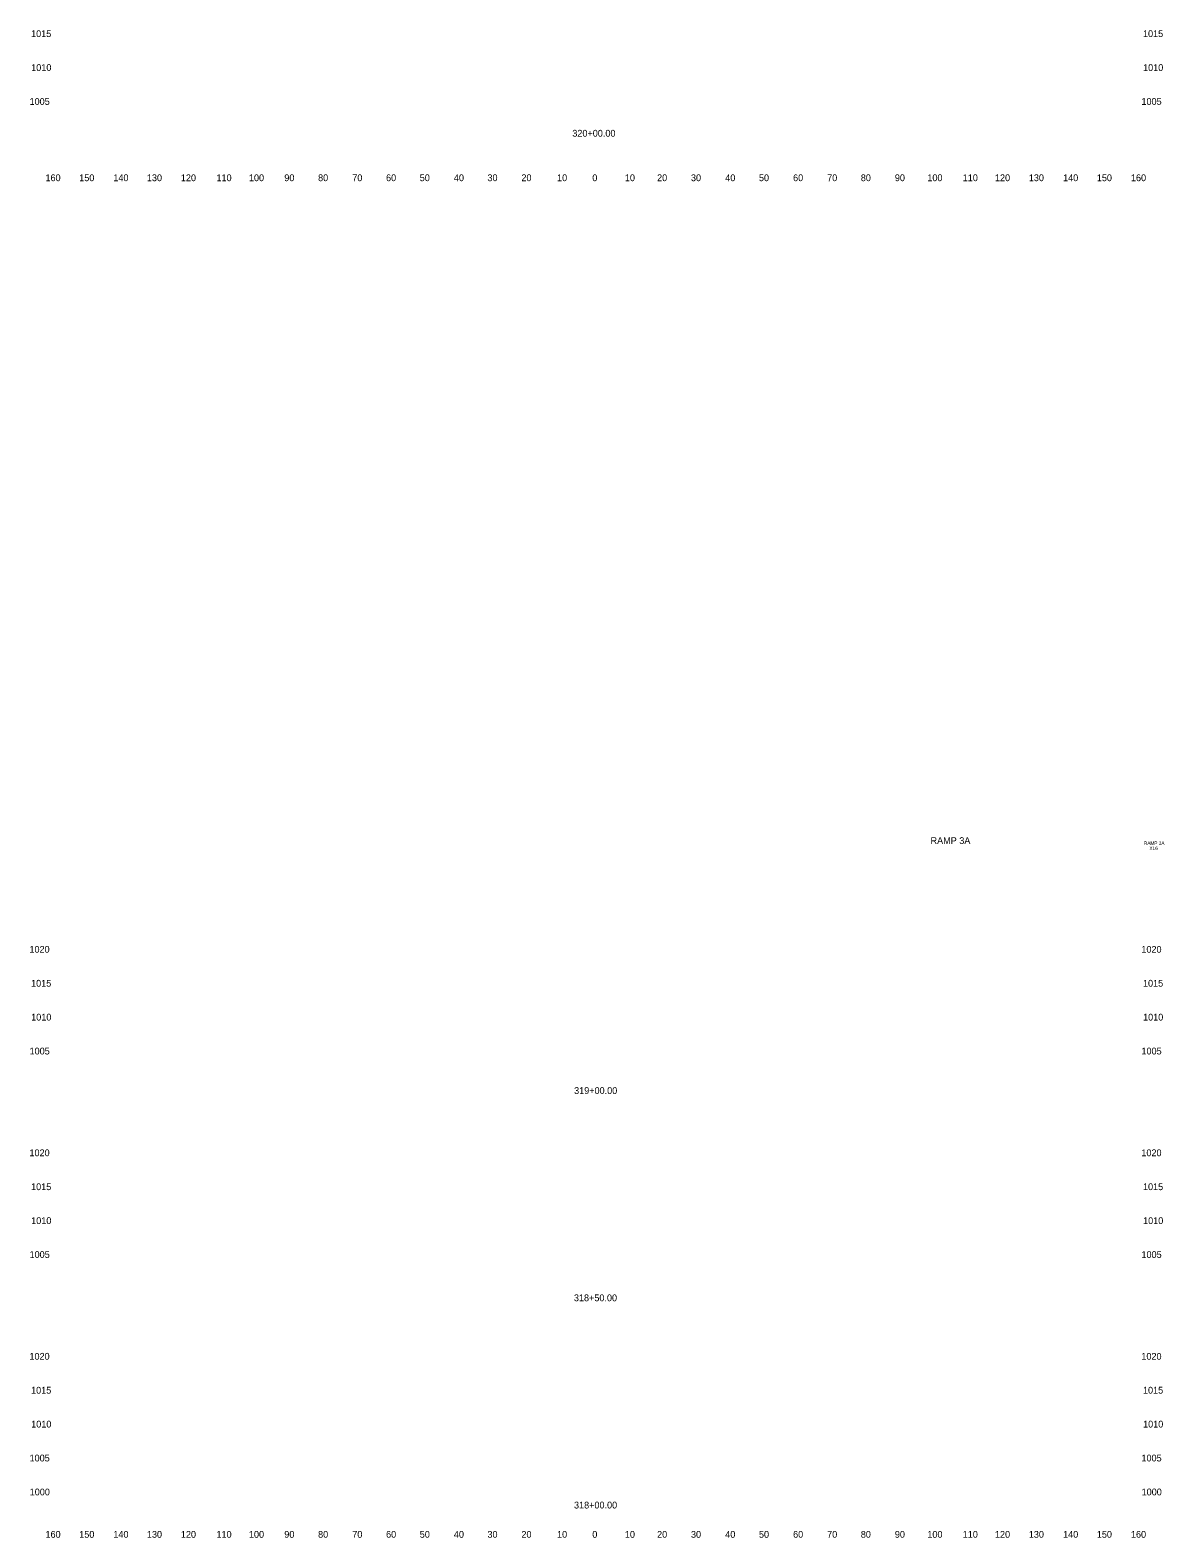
# Model space of a CAD drawing. Extents: x 4286 to 5843, y 4997 to 8804.
# Drawn here: x 5508.6 to 5842.8, y 6997.5 to 7442 of the extents above; entities that cross this region are included whole.
import ezdxf

# ---------------------------------------------------------------- set-up
doc = ezdxf.new("R2010")
doc.units = 0
for name, color, linetype in [('RD_SHT_ID', 7, 'Continuous'), ('RD_XS_TX_Offset', 7, 'Continuous'), ('RD_XS_TX_Station', 7, 'Continuous')]:
    doc.layers.add(name, color=color, linetype=linetype)

msp = doc.modelspace()

# ---------------------------------------------------------------- texts
at = {"layer": 'RD_SHT_ID'}
for s, height, p in [('RAMP 3A', 2, (5774.02, 7202.06)), ('RAMP 3A', 1, (5836.93, 7201.8)), ('X16', 1, (5838.55, 7200.3))]:
    msp.add_text(s, height=height, dxfattribs=at).set_placement(p)
at = {"layer": 'RD_XS_TX_Offset'}
for s, p in [('1015', (5508.85, 7440)), ('1015', (5836.65, 7440)), ('1010', (5508.88, 7430)), ('1010', (5836.68, 7430)), ('1005', (5508.4, 7420)), ('1005', (5836.2, 7420)), ('160', (5513.1, 7397.5)), ('150', (5523.04, 7397.5)), ('140', (5533.1, 7397.5)), ('130', (5542.99, 7397.5)), ('120', (5553.01, 7397.5)), ('110', (5563.51, 7397.5)), ('100', (5573.07, 7397.5)), ('90', (5583.5, 7397.5)), ('80', (5593.46, 7397.5)), ('70', (5603.54, 7397.5)), ('60', (5613.5, 7397.5)), ('50', (5623.43, 7397.5)), ('40', (5633.5, 7397.5)), ('30', (5643.39, 7397.5)), ('20', (5653.4, 7397.5)), ('10', (5663.91, 7397.5)), ('0', (5674.3, 7397.5)), ('0', (5674.3, 7397.5)), ('10', (5683.91, 7397.5)), ('20', (5693.4, 7397.5)), ('30', (5703.39, 7397.5)), ('40', (5713.5, 7397.5)), ('50', (5723.43, 7397.5)), ('60', (5733.5, 7397.5)), ('70', (5743.54, 7397.5)), ('80', (5753.46, 7397.5)), ('90', (5763.5, 7397.5)), ('100', (5773.07, 7397.5)), ('110', (5783.51, 7397.5)), ('120', (5793.01, 7397.5)), ('130', (5802.99, 7397.5)), ('140', (5813.1, 7397.5)), ('150', (5823.04, 7397.5)), ('160', (5833.1, 7397.5)), ('1020', (5508.37, 7170)), ('1020', (5836.17, 7170)), ('1015', (5508.85, 7160)), ('1015', (5836.65, 7160)), ('1010', (5508.88, 7150)), ('1010', (5836.68, 7150)), ('1005', (5508.4, 7140)), ('1005', (5836.2, 7140)), ('1020', (5508.37, 7110)), ('1020', (5836.17, 7110)), ('1015', (5508.85, 7100)), ('1015', (5836.65, 7100)), ('1010', (5508.88, 7090)), ('1010', (5836.68, 7090)), ('1005', (5508.4, 7080)), ('1005', (5836.2, 7080)), ('1020', (5508.37, 7050)), ('1020', (5836.17, 7050)), ('1015', (5508.85, 7040)), ('1015', (5836.65, 7040)), ('1010', (5508.88, 7030)), ('1010', (5836.68, 7030)), ('1005', (5508.4, 7020)), ('1005', (5836.2, 7020)), ('1000', (5508.44, 7010)), ('1000', (5836.24, 7010)), ('160', (5513.1, 6997.5)), ('150', (5523.04, 6997.5)), ('140', (5533.1, 6997.5)), ('130', (5542.99, 6997.5)), ('120', (5553.01, 6997.5)), ('110', (5563.51, 6997.5)), ('100', (5573.07, 6997.5)), ('90', (5583.5, 6997.5)), ('80', (5593.46, 6997.5)), ('70', (5603.54, 6997.5)), ('60', (5613.5, 6997.5)), ('50', (5623.43, 6997.5)), ('40', (5633.5, 6997.5)), ('30', (5643.39, 6997.5)), ('20', (5653.4, 6997.5)), ('10', (5663.91, 6997.5)), ('0', (5674.3, 6997.5)), ('0', (5674.3, 6997.5)), ('10', (5683.91, 6997.5)), ('20', (5693.4, 6997.5)), ('30', (5703.39, 6997.5)), ('40', (5713.5, 6997.5)), ('50', (5723.43, 6997.5)), ('60', (5733.5, 6997.5)), ('70', (5743.54, 6997.5)), ('80', (5753.46, 6997.5)), ('90', (5763.5, 6997.5)), ('100', (5773.07, 6997.5)), ('110', (5783.51, 6997.5)), ('120', (5793.01, 6997.5)), ('130', (5802.99, 6997.5)), ('140', (5813.1, 6997.5)), ('150', (5823.04, 6997.5)), ('160', (5833.1, 6997.5))]:
    msp.add_text(s, height=2, dxfattribs=at).set_placement(p)
at = {"layer": 'RD_XS_TX_Station'}
for s, p in [('320+00.00', (5668.41, 7410.63)), ('319+00.00', (5668.94, 7128.36)), ('318+50.00', (5668.88, 7067.24)), ('318+00.00', (5668.91, 7006.13))]:
    msp.add_text(s, height=2, dxfattribs=at).set_placement(p)

doc.saveas('drawing.dxf')
